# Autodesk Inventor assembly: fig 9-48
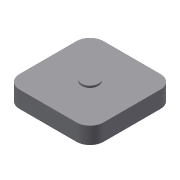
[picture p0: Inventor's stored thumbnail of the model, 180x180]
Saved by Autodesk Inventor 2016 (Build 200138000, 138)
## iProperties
Created: 2013-07
Part Number: fig 9-48
Document SubType Name: Assembly
Designer: CADCIM
Author: CADCIM
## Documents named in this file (3)
- D:\KAVITA\Autodesk Inventor_ 2016 Project_Kavita\Inventor_Part Files\Inventor_2016_Part\c09_Inv_2016\c09_inv_2016_prt\fig 9-48.iam
- D:\KAVITA\Autodesk Inventor_ 2016 Project_Kavita\Inventor_Part Files\Inventor_2016_Part\c09_Inv_2016\c09_inv_2016_prt\17 (1).ipt
- D:\KAVITA\Autodesk Inventor_ 2016 Project_Kavita\Inventor_Part Files\Inventor_2016_Part\c09_Inv_2016\c09_inv_2016_prt\18.ipt
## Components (2 placed, 2 different names)
1. 17 (1):1 — Planar:1
2. 18:1 — Planar:1
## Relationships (1: PlanarJoint 1)
- Planar:1: 17 (1):1 ↔ 18:1
